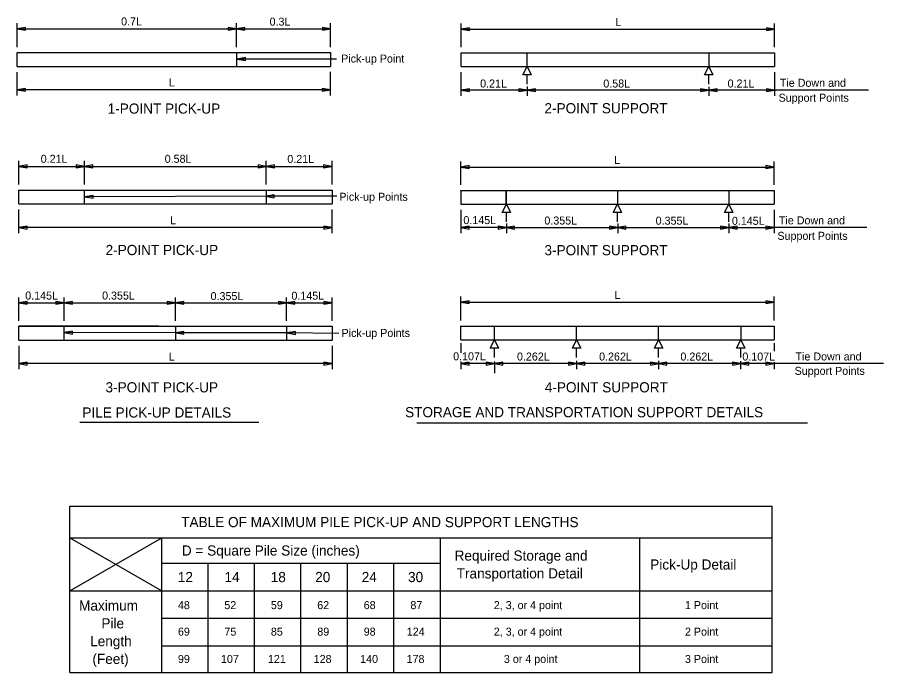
# Model space of a CAD drawing. Extents: x 112309.5 to 112344.2, y 111905.2 to 111923.
# Drawn here: x 112310.51 to 112321.42, y 111912.67 to 111920.92 of the extents above; entities that cross this region are included whole.
import ezdxf

# ---------------------------------------------------------------- set-up
doc = ezdxf.new("R2010")
doc.units = 0
for name, color, linetype in [('Dimension', 7, 'Continuous'), ('PileConc', 7, 'Continuous'), ('TextStructures', 7, 'Continuous')]:
    doc.layers.add(name, color=color, linetype=linetype)

msp = doc.modelspace()

# ---------------------------------------------------------------- linework, layer by layer
at = {"layer": 'Dimension'}
for p, q in [((112310.509, 111920.544), (112310.509, 111920.844)), ((112313.27, 111920.544), (112313.27, 111920.844)), ((112314.454, 111920.544), (112314.454, 111920.844)), ((112316.1, 111920.542), (112316.1, 111920.839)), ((112320.045, 111920.542), (112320.045, 111920.839)), ((112310.509, 111920.774), (112313.27, 111920.774)), ((112313.27, 111920.774), (112314.454, 111920.774)), ((112316.1, 111920.769), (112320.045, 111920.769)), ((112314.529, 111920.393), (112313.279, 111920.393)), ((112310.509, 111919.935), (112310.509, 111920.229)), ((112314.454, 111919.935), (112314.454, 111920.23)), ((112316.1, 111919.93), (112316.1, 111920.228)), ((112316.929, 111920.078), (112316.929, 111920.194)), ((112319.218, 111920.078), (112319.218, 111920.194)), ((112320.045, 111920.228), (112320.045, 111919.93)), ((112316.929, 111920.045), (112316.929, 111919.93)), ((112319.217, 111920.044), (112319.217, 111919.93)), ((112314.454, 111920.005), (112310.509, 111920.005)), ((112316.929, 111920), (112316.1, 111920)), ((112319.217, 111920), (112316.929, 111920)), ((112320.045, 111920), (112319.217, 111920)), ((112321.226, 111920), (112320.045, 111920)), ((112310.528, 111918.812), (112310.528, 111919.111)), ((112310.528, 111919.041), (112311.356, 111919.041)), ((112311.356, 111918.812), (112311.356, 111919.111)), ((112311.356, 111919.041), (112313.644, 111919.041)), ((112313.644, 111918.812), (112313.644, 111919.111)), ((112313.644, 111919.041), (112314.469, 111919.041)), ((112314.473, 111918.812), (112314.473, 111919.111)), ((112316.095, 111918.808), (112316.095, 111919.102)), ((112320.039, 111918.808), (112320.039, 111919.102)), ((112316.095, 111919.032), (112320.039, 111919.032)), ((112316.095, 111918.738), (112316.095, 111918.742)), ((112316.666, 111918.738), (112316.666, 111918.74)), ((112318.067, 111918.738), (112318.067, 111918.741)), ((112313.639, 111918.665), (112311.359, 111918.657)), ((112314.532, 111918.665), (112313.639, 111918.665)), ((112310.528, 111918.2), (112310.528, 111918.497)), ((112314.473, 111918.2), (112314.473, 111918.497)), ((112316.095, 111918.494), (112316.095, 111918.2)), ((112320.039, 111918.494), (112320.039, 111918.2)), ((112316.668, 111918.344), (112316.668, 111918.46)), ((112318.068, 111918.344), (112318.068, 111918.46)), ((112319.469, 111918.344), (112319.469, 111918.46)), ((112316.667, 111918.321), (112316.667, 111918.2)), ((112318.069, 111918.321), (112318.069, 111918.2)), ((112319.469, 111918.321), (112319.469, 111918.2)), ((112314.473, 111918.27), (112310.528, 111918.27)), ((112316.667, 111918.27), (112316.095, 111918.27)), ((112316.667, 111918.27), (112318.069, 111918.27)), ((112318.069, 111918.27), (112319.469, 111918.27)), ((112319.469, 111918.27), (112320.039, 111918.27)), ((112321.206, 111918.27), (112320.039, 111918.27)), ((112316.095, 111917.099), (112316.095, 111917.403)), ((112320.039, 111917.099), (112320.039, 111917.403)), ((112310.528, 111917.097), (112310.528, 111917.392)), ((112310.528, 111917.322), (112311.099, 111917.322)), ((112311.099, 111917.097), (112311.099, 111917.392)), ((112311.099, 111917.322), (112312.5, 111917.322)), ((112312.5, 111917.097), (112312.5, 111917.392)), ((112312.5, 111917.322), (112313.9, 111917.322)), ((112313.9, 111917.097), (112313.9, 111917.392)), ((112313.9, 111917.322), (112314.473, 111917.322)), ((112314.473, 111917.097), (112314.473, 111917.392)), ((112316.095, 111917.333), (112320.039, 111917.333)), ((112316.095, 111917.029), (112316.095, 111917.033)), ((112316.666, 111917.029), (112316.666, 111917.031)), ((112318.067, 111917.029), (112318.067, 111917.032)), ((112312.504, 111916.945), (112311.1, 111916.948)), ((112313.907, 111916.945), (112312.504, 111916.945)), ((112314.556, 111916.936), (112313.907, 111916.945)), ((112310.528, 111916.783), (112310.528, 111916.487)), ((112314.473, 111916.783), (112314.473, 111916.487)), ((112316.095, 111916.815), (112316.095, 111916.695)), ((112316.518, 111916.635), (112316.518, 111916.751)), ((112317.551, 111916.635), (112317.551, 111916.751)), ((112318.584, 111916.635), (112318.584, 111916.751)), ((112319.619, 111916.635), (112319.619, 111916.751)), ((112320.039, 111916.815), (112320.039, 111916.716)), ((112314.473, 111916.557), (112310.528, 111916.557)), ((112316.095, 111916.583), (112316.095, 111916.487)), ((112316.518, 111916.557), (112316.095, 111916.557)), ((112316.517, 111916.584), (112316.517, 111916.437)), ((112317.552, 111916.557), (112316.518, 111916.557)), ((112317.55, 111916.591), (112317.55, 111916.487)), ((112318.585, 111916.557), (112317.552, 111916.557)), ((112318.584, 111916.591), (112318.584, 111916.487)), ((112319.617, 111916.557), (112318.585, 111916.557)), ((112319.617, 111916.59), (112319.617, 111916.487)), ((112320.038, 111916.557), (112319.617, 111916.557)), ((112321.418, 111916.557), (112320.038, 111916.557)), ((112320.039, 111916.576), (112320.039, 111916.487)), ((112316.517, 111916.519), (112316.517, 111916.487)), ((112318.585, 111916.487), (112318.585, 111916.487)), ((112313.55, 111915.814), (112311.298, 111915.814)), ((112315.539, 111915.811), (112320.458, 111915.811)), ((112311.172, 111912.666), (112311.172, 111914.762)), ((112311.172, 111914.762), (112320.016, 111914.762)), ((112320.016, 111912.666), (112320.016, 111914.762)), ((112311.172, 111914.362), (112320.016, 111914.362)), ((112311.172, 111913.695), (112312.327, 111914.362)), ((112311.172, 111914.362), (112312.327, 111913.695)), ((112312.327, 111912.666), (112312.327, 111914.362)), ((112315.836, 111912.666), (112315.836, 111914.362)), ((112318.349, 111912.666), (112318.349, 111914.362)), ((112312.327, 111914.045), (112315.836, 111914.045)), ((112312.911, 111912.666), (112312.911, 111914.045)), ((112313.496, 111912.666), (112313.496, 111914.045)), ((112314.081, 111912.666), (112314.081, 111914.045)), ((112314.666, 111912.666), (112314.666, 111914.045)), ((112315.251, 111912.666), (112315.251, 111914.045)), ((112311.172, 111913.695), (112320.016, 111913.695)), ((112312.327, 111913.35), (112320.016, 111913.35)), ((112312.327, 111913.005), (112320.016, 111913.005)), ((112311.172, 111912.666), (112320.016, 111912.666))]:
    msp.add_line(p, q, dxfattribs=at)
for points in [[(112310.509, 111920.774), (112310.614, 111920.756), (112310.614, 111920.791)], [(112313.27, 111920.774), (112313.166, 111920.791), (112313.166, 111920.756)], [(112313.27, 111920.774), (112313.374, 111920.756), (112313.374, 111920.791)], [(112314.454, 111920.774), (112314.35, 111920.791), (112314.35, 111920.756)], [(112316.1, 111920.769), (112316.204, 111920.751), (112316.204, 111920.787)], [(112320.045, 111920.769), (112319.941, 111920.787), (112319.941, 111920.751)], [(112313.264, 111920.392), (112313.282, 111920.389), (112313.282, 111920.395)], [(112313.279, 111920.393), (112313.383, 111920.375), (112313.383, 111920.411)], [(112316.929, 111920.298), (112316.981, 111920.194), (112316.876, 111920.194)], [(112319.217, 111920.298), (112319.269, 111920.194), (112319.164, 111920.194)], [(112310.509, 111920.005), (112310.614, 111919.987), (112310.614, 111920.022)], [(112314.454, 111920.005), (112314.349, 111920.022), (112314.349, 111919.987)], [(112316.1, 111920), (112316.204, 111919.982), (112316.204, 111920.018)], [(112316.929, 111920), (112316.824, 111920.018), (112316.824, 111919.982)], [(112316.929, 111920), (112317.033, 111919.982), (112317.033, 111920.018)], [(112319.217, 111920), (112319.113, 111920.018), (112319.113, 111919.982)], [(112319.217, 111920), (112319.321, 111919.982), (112319.321, 111920.018)], [(112320.045, 111920), (112319.941, 111920.018), (112319.941, 111919.982)], [(112310.528, 111919.041), (112310.632, 111919.024), (112310.632, 111919.059)], [(112311.356, 111919.041), (112311.252, 111919.059), (112311.252, 111919.024)], [(112311.356, 111919.041), (112311.46, 111919.024), (112311.46, 111919.059)], [(112313.644, 111919.041), (112313.54, 111919.059), (112313.54, 111919.024)], [(112313.644, 111919.041), (112313.749, 111919.024), (112313.749, 111919.059)], [(112314.469, 111919.041), (112314.364, 111919.059), (112314.364, 111919.024)], [(112316.095, 111919.032), (112316.199, 111919.014), (112316.199, 111919.05)], [(112320.039, 111919.032), (112319.935, 111919.05), (112319.935, 111919.014)], [(112311.359, 111918.657), (112311.464, 111918.639), (112311.463, 111918.675)], [(112313.639, 111918.665), (112313.744, 111918.647), (112313.744, 111918.683)], [(112316.667, 111918.564), (112316.719, 111918.46), (112316.614, 111918.46)], [(112318.067, 111918.564), (112318.119, 111918.46), (112318.014, 111918.46)], [(112319.468, 111918.564), (112319.52, 111918.46), (112319.415, 111918.46)], [(112310.528, 111918.27), (112310.632, 111918.252), (112310.632, 111918.287)], [(112314.473, 111918.27), (112314.369, 111918.287), (112314.369, 111918.252)], [(112316.095, 111918.27), (112316.199, 111918.252), (112316.199, 111918.287)], [(112316.667, 111918.27), (112316.563, 111918.287), (112316.563, 111918.252)], [(112316.667, 111918.27), (112316.771, 111918.252), (112316.771, 111918.287)], [(112318.069, 111918.27), (112317.964, 111918.287), (112317.964, 111918.252)], [(112318.069, 111918.27), (112318.173, 111918.252), (112318.173, 111918.287)], [(112319.469, 111918.27), (112319.365, 111918.287), (112319.365, 111918.252)], [(112319.469, 111918.27), (112319.574, 111918.252), (112319.574, 111918.287)], [(112320.039, 111918.27), (112319.935, 111918.287), (112319.935, 111918.252)], [(112310.528, 111917.322), (112310.632, 111917.304), (112310.632, 111917.34)], [(112311.099, 111917.322), (112310.995, 111917.34), (112310.995, 111917.304)], [(112311.099, 111917.322), (112311.204, 111917.304), (112311.204, 111917.34)], [(112312.5, 111917.322), (112312.396, 111917.34), (112312.396, 111917.304)], [(112312.5, 111917.322), (112312.604, 111917.304), (112312.604, 111917.34)], [(112313.9, 111917.322), (112313.796, 111917.34), (112313.796, 111917.304)], [(112313.9, 111917.322), (112314.004, 111917.304), (112314.004, 111917.34)], [(112314.473, 111917.322), (112314.369, 111917.34), (112314.369, 111917.304)], [(112316.095, 111917.333), (112316.199, 111917.315), (112316.199, 111917.35)], [(112320.039, 111917.333), (112319.935, 111917.35), (112319.935, 111917.315)], [(112311.1, 111916.948), (112311.204, 111916.93), (112311.204, 111916.965)], [(112312.504, 111916.945), (112312.608, 111916.927), (112312.608, 111916.962)], [(112313.907, 111916.945), (112314.011, 111916.926), (112314.011, 111916.961)], [(112316.517, 111916.855), (112316.569, 111916.751), (112316.464, 111916.751)], [(112317.55, 111916.855), (112317.603, 111916.751), (112317.498, 111916.751)], [(112318.584, 111916.855), (112318.636, 111916.751), (112318.531, 111916.751)], [(112319.618, 111916.855), (112319.67, 111916.751), (112319.565, 111916.751)], [(112310.528, 111916.557), (112310.632, 111916.539), (112310.632, 111916.574)], [(112314.473, 111916.557), (112314.369, 111916.574), (112314.369, 111916.539)], [(112316.095, 111916.557), (112316.199, 111916.539), (112316.199, 111916.574)], [(112316.518, 111916.557), (112316.414, 111916.574), (112316.414, 111916.539)], [(112316.518, 111916.557), (112316.622, 111916.539), (112316.622, 111916.574)], [(112317.552, 111916.557), (112317.448, 111916.574), (112317.448, 111916.539)], [(112317.552, 111916.557), (112317.656, 111916.539), (112317.656, 111916.574)], [(112318.585, 111916.557), (112318.481, 111916.574), (112318.481, 111916.539)], [(112318.585, 111916.557), (112318.689, 111916.539), (112318.689, 111916.574)], [(112319.617, 111916.557), (112319.513, 111916.574), (112319.513, 111916.539)], [(112319.617, 111916.557), (112319.721, 111916.539), (112319.721, 111916.574)], [(112320.038, 111916.557), (112319.934, 111916.574), (112319.934, 111916.539)]]:
    msp.add_lwpolyline(points, close=True, dxfattribs=at)
at = {"layer": 'PileConc'}
for p, q in [((112310.509, 111920.474), (112314.454, 111920.474)), ((112310.509, 111920.3), (112310.509, 111920.474)), ((112313.27, 111920.474), (112313.27, 111920.3)), ((112314.454, 111920.474), (112314.454, 111920.3)), ((112316.1, 111920.472), (112320.045, 111920.472)), ((112316.1, 111920.298), (112316.1, 111920.472)), ((112316.929, 111920.298), (112316.929, 111920.472)), ((112319.217, 111920.472), (112319.217, 111920.298)), ((112320.045, 111920.472), (112320.045, 111920.298)), ((112310.509, 111920.3), (112314.454, 111920.3)), ((112316.1, 111920.298), (112320.045, 111920.298)), ((112310.528, 111918.742), (112314.473, 111918.742)), ((112310.528, 111918.568), (112310.528, 111918.742)), ((112311.356, 111918.568), (112311.356, 111918.742)), ((112313.644, 111918.742), (112313.644, 111918.568)), ((112314.473, 111918.742), (112314.473, 111918.568)), ((112316.095, 111918.738), (112320.039, 111918.738)), ((112316.095, 111918.738), (112316.095, 111918.564)), ((112316.666, 111918.564), (112316.666, 111918.738)), ((112316.667, 111918.564), (112316.667, 111918.738)), ((112318.067, 111918.738), (112318.067, 111918.564)), ((112318.141, 111918.738), (112320.039, 111918.738)), ((112319.468, 111918.738), (112319.468, 111918.564)), ((112320.039, 111918.738), (112320.039, 111918.564)), ((112310.528, 111918.568), (112314.473, 111918.568)), ((112316.095, 111918.564), (112320.039, 111918.564)), ((112310.528, 111917.027), (112314.473, 111917.027)), ((112312.287, 111917.027), (112310.528, 111917.027)), ((112310.528, 111916.853), (112310.528, 111917.027)), ((112311.099, 111916.853), (112311.099, 111917.027)), ((112312.5, 111917.027), (112312.5, 111916.853)), ((112313.9, 111917.027), (112313.9, 111916.853)), ((112314.473, 111917.027), (112314.473, 111916.853)), ((112316.095, 111917.029), (112320.039, 111917.029)), ((112316.095, 111916.855), (112316.095, 111917.029)), ((112316.517, 111916.855), (112316.517, 111917.029)), ((112317.55, 111916.855), (112317.55, 111917.029)), ((112318.141, 111917.029), (112320.039, 111917.029)), ((112318.584, 111916.855), (112318.584, 111917.029)), ((112319.618, 111917.029), (112319.618, 111916.855)), ((112320.039, 111917.029), (112320.039, 111916.855)), ((112310.528, 111916.853), (112314.473, 111916.853)), ((112316.095, 111916.855), (112320.039, 111916.855))]:
    msp.add_line(p, q, dxfattribs=at)

# ---------------------------------------------------------------- texts
at = {"layer": 'Dimension'}
for s, p in [('Required Storage and', (112316.015, 111914.076)), ('Transportation Detail  ', (112316.042, 111913.852)), ('Maximum', (112311.287, 111913.447)), ('Pile', (112311.568, 111913.223)), ('Length', (112311.426, 111912.999)), ('(Feet)', (112311.455, 111912.775))]:
    msp.add_text(s, height=0.128, dxfattribs=at).set_placement(p)
at = {"layer": 'TextStructures'}
for s, height, p in [('0.7L', 0.1008, (112311.816, 111920.816)), ('0.3L', 0.1008, (112313.686, 111920.813)), ('L', 0.101, (112318.04, 111920.807)), ('Pick-up Point', 0.1008, (112314.587, 111920.348)), ('L', 0.101, (112312.418, 111920.047)), ('0.21L', 0.1008, (112316.337, 111920.034)), ('0.58L', 0.1008, (112317.888, 111920.034)), ('0.21L', 0.1008, (112319.453, 111920.034)), ('Tie Down and', 0.1008, (112320.111, 111920.043)), ('Support Points', 0.1008, (112320.095, 111919.855)), ('1-POINT PICK-UP', 0.128, (112311.647, 111919.705)), ('2-POINT SUPPORT', 0.128, (112317.147, 111919.709)), ('0.21L', 0.1008, (112310.804, 111919.086)), ('0.58L', 0.1008, (112312.365, 111919.086)), ('0.21L', 0.1008, (112313.909, 111919.084)), ('L', 0.101, (112318.025, 111919.072)), ('Pick-up Points', 0.1008, (112314.564, 111918.608)), ('L', 0.101, (112312.433, 111918.312)), ('0.145L', 0.1008, (112316.126, 111918.314)), ('0.355L', 0.1008, (112317.146, 111918.309)), ('0.355L', 0.1008, (112318.547, 111918.307)), ('0.145L', 0.1008, (112319.507, 111918.305)), ('Tie Down and', 0.1008, (112320.099, 111918.311)), ('Support Points', 0.1008, (112320.08, 111918.116)), ('2-POINT PICK-UP', 0.128, (112311.621, 111917.924)), ('3-POINT SUPPORT', 0.128, (112317.147, 111917.922)), ('0.145L', 0.1008, (112310.609, 111917.364)), ('0.355L', 0.1008, (112311.577, 111917.364)), ('0.355L', 0.1008, (112312.943, 111917.357)), ('0.145L', 0.1008, (112313.961, 111917.362)), ('L', 0.101, (112318.03, 111917.372)), ('Pick-up Points', 0.1008, (112314.592, 111916.893)), ('L', 0.101, (112312.416, 111916.595)), ('0.107L', 0.1008, (112315.997, 111916.599)), ('0.262L', 0.1008, (112316.801, 111916.596)), ('0.262L', 0.1008, (112317.835, 111916.596)), ('0.262L', 0.1008, (112318.859, 111916.596)), ('0.107L', 0.1008, (112319.639, 111916.596)), ('Tie Down and', 0.1008, (112320.308, 111916.597)), ('Support Points', 0.1008, (112320.297, 111916.416)), ('3-POINT PICK-UP', 0.128, (112311.62, 111916.195)), ('4-POINT SUPPORT', 0.128, (112317.151, 111916.195)), ('PILE PICK-UP DETAILS', 0.128, (112311.328, 111915.878)), ('STORAGE AND TRANSPORTATION SUPPORT DETAILS', 0.128, (112315.392, 111915.882)), ('TABLE OF MAXIMUM PILE PICK-UP AND SUPPORT LENGTHS', 0.128, (112312.573, 111914.498)), ('D = Square Pile Size (inches)', 0.128, (112312.581, 111914.14)), ('Pick-Up Detail', 0.128, (112318.479, 111913.964)), ('12', 0.128, (112312.53, 111913.806)), ('14', 0.128, (112313.118, 111913.806)), ('18', 0.128, (112313.7, 111913.806)), ('20', 0.128, (112314.26, 111913.806)), ('24', 0.128, (112314.846, 111913.806)), ('30', 0.128, (112315.429, 111913.806)), ('48', 0.1008, (112312.532, 111913.466)), ('52', 0.1008, (112313.116, 111913.466)), ('59', 0.1008, (112313.702, 111913.466)), ('62', 0.1008, (112314.286, 111913.466)), ('68', 0.1008, (112314.871, 111913.466)), ('87', 0.1008, (112315.459, 111913.466)), ('2, 3, or 4 point', 0.1008, (112316.509, 111913.466)), ('1 Point', 0.1008, (112318.916, 111913.466)), ('69', 0.1008, (112312.532, 111913.132)), ('75', 0.1008, (112313.117, 111913.132)), ('85', 0.1008, (112313.702, 111913.132)), ('89', 0.1008, (112314.287, 111913.132)), ('98', 0.1008, (112314.871, 111913.132)), ('124', 0.1008, (112315.413, 111913.132)), ('2, 3, or 4 point', 0.1008, (112316.509, 111913.132)), ('2 Point', 0.1008, (112318.916, 111913.132)), ('99', 0.1008, (112312.532, 111912.788)), ('107', 0.1008, (112313.074, 111912.788)), ('121', 0.1008, (112313.665, 111912.788)), ('128', 0.1008, (112314.241, 111912.788)), ('140', 0.1008, (112314.826, 111912.788)), ('178', 0.1008, (112315.411, 111912.788)), ('3 or 4 point', 0.1008, (112316.636, 111912.788)), ('3 Point', 0.1008, (112318.916, 111912.788))]:
    msp.add_text(s, height=height, dxfattribs=at).set_placement(p)

doc.saveas('drawing.dxf')
